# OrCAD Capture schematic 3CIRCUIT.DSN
size A
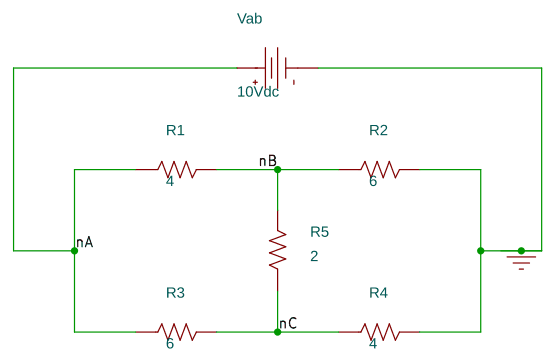
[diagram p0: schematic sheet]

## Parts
R1  4  [AXRC05]
R2  6  [AXRC05]
R3  6  [AXRC05]
R4  4  [AXRC05]
R5  2  [AXRC05]
Vab  VDC

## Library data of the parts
R1-R5 = R
Vab = VDC: DC: 10Vdc

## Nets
0: R2.2 R4.2 Vab.1(-)
nA: R1.1 R3.1 Vab.0(+)
nB: R1.2 R2.1 R5.2
nC: R3.2 R4.1 R5.1
